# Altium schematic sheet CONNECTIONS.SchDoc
size A4; PageSetup: Record=PageOptions|CenterHorizontal=True|CenterVertical=True|PrintScale=0.70|XCorrection=1.00|YCorrection=1.00|PrintKind=0|BorderSize=5000000|LeftOffset=5|BottomOffset=0|Orientation=1|PaperLength=1000|PaperWidth=1000|Scale=100|PaperSource=7|PrintQuality=-4|MediaType=1|DitherType=10|PaperKind=A4|PrintScaleMode=1
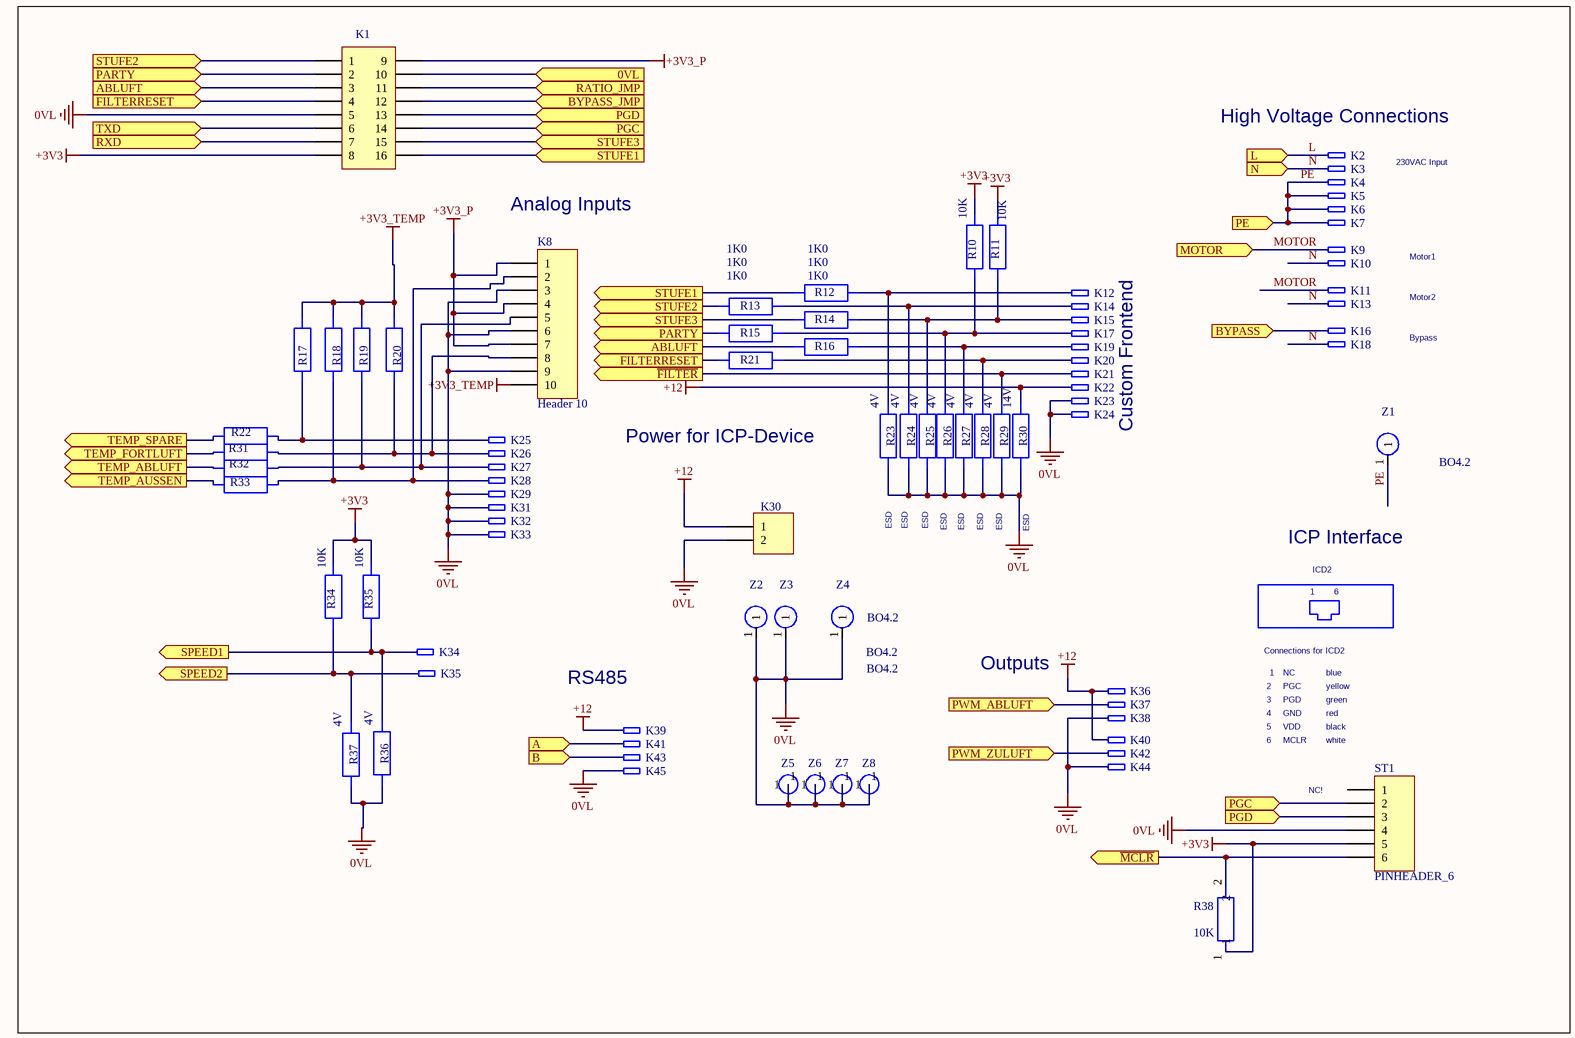
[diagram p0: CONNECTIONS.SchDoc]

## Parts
K1  PINHEADER_SMD_2MM_16POL_1  [PINHEADER_SMD_2MM_16POL]  (value not drawn)
K2  WAGO-236  [KL02X196Y0A0]  (value not drawn)
K3  WAGO-236  [KL02X196Y0A0]  (value not drawn)
K4  WAGO-236  [KL02X196Y0A0]  (value not drawn)
K5  WAGO-236  [KL02X196Y0A0]  (value not drawn)
K6  WAGO-236  [KL02X196Y0A0]  (value not drawn)
K7  WAGO-236  [KL02X196Y0A0]  (value not drawn)
K8  Header 10  [HDR1X10]
K9  WAGO-236  [KL02X196Y0A0]  (value not drawn)
K10  WAGO-236  [KL02X196Y0A0]  (value not drawn)
K11  WAGO-236  [KL02X196Y0A0]  (value not drawn)
K12  WAGO-236  [KL02X196Y0A0]  (value not drawn)
K13  WAGO-236  [KL02X196Y0A0]  (value not drawn)
K14  WAGO-236  [KL02X196Y0A0]  (value not drawn)
K15  WAGO-236  [KL02X196Y0A0]  (value not drawn)
K16  WAGO-236  [KL02X196Y0A0]  (value not drawn)
K17  WAGO-236  [KL02X196Y0A0]  (value not drawn)
K18  WAGO-236  [KL02X196Y0A0]  (value not drawn)
K19  WAGO-236  [KL02X196Y0A0]  (value not drawn)
K20  WAGO-236  [KL02X196Y0A0]  (value not drawn)
K21  WAGO-236  [KL02X196Y0A0]  (value not drawn)
K22  WAGO-236  [KL02X196Y0A0]  (value not drawn)
K23  WAGO-236  [KL02X196Y0A0]  (value not drawn)
K24  WAGO-236  [KL02X196Y0A0]  (value not drawn)
K25  WAGO-233  [KL02X0Y197A0]  (value not drawn)
K26  WAGO-233  [KL02X0Y197A0]  (value not drawn)
K27  WAGO-233  [KL02X0Y197A0]  (value not drawn)
K28  WAGO-233  [KL02X0Y197A0]  (value not drawn)
K29  WAGO-233  [KL02X0Y197A0]  (value not drawn)
K30  WUERTH_61900211121  (value not drawn)
K31  WAGO-233  [KL02X0Y197A0]  (value not drawn)
K32  WAGO-233  [KL02X0Y197A0]  (value not drawn)
K33  WAGO-233  [KL02X0Y197A0]  (value not drawn)
K34  WAGO-233  [KL02X0Y197A0]  (value not drawn)
K35  WAGO-233  [KL02X0Y197A0]  (value not drawn)
K36  WAGO-233  [KL02X0Y197A0]  (value not drawn)
K37  WAGO-233  [KL02X0Y197A0]  (value not drawn)
K38  WAGO-233  [KL02X0Y197A0]  (value not drawn)
K39  WAGO-233  [KL02X0Y197A0]  (value not drawn)
K40  WAGO-233  [KL02X0Y197A0]  (value not drawn)
K41  WAGO-233  [KL02X0Y197A0]  (value not drawn)
K42  WAGO-233  [KL02X0Y197A0]  (value not drawn)
K43  WAGO-233  [KL02X0Y197A0]  (value not drawn)
K44  WAGO-233  [KL02X0Y197A0]  (value not drawn)
K45  WAGO-233  [KL02X0Y197A0]  (value not drawn)
R10  value 10K  (hidden comment: R12/10K)
R11  value 10K  (hidden comment: R12/10K)
R12  value 1K0  (hidden comment: R12/1K0)
R13  value 1K0  (hidden comment: R12/1K0)
R14  value 1K0  (hidden comment: R12/1K0)
R15  value 1K0  (hidden comment: R12/1K0)
R16  value 1K0  (hidden comment: R12/1K0)
R17  R12/2K0  (value not drawn)
R18  R12/2K0  (value not drawn)
R19  R12/2K0  (value not drawn)
R20  R12/2K0  (value not drawn)
R21  value 1K0  (hidden comment: R12/1K0)
R22  R12/0R  (value not drawn)
R23  value 4V  (hidden comment: R12/VARISTOR_4V)
R24  value 4V  (hidden comment: R12/VARISTOR_4V)
R25  value 4V  (hidden comment: R12/VARISTOR_4V)
R26  value 4V  (hidden comment: R12/VARISTOR_4V)
R27  value 4V  (hidden comment: R12/VARISTOR_4V)
R28  value 4V  (hidden comment: R12/VARISTOR_4V)
R29  value 4V  (hidden comment: R12/VARISTOR_4V)
R30  value 14V  (hidden comment: R12/VARISTOR_14V)
R31  R12/0R  (value not drawn)
R32  R12/0R  (value not drawn)
R33  R12/0R  (value not drawn)
R34  value 10K  (hidden comment: R12/10K)
R35  value 10K  (hidden comment: R12/10K)
R36  value 4V  (hidden comment: R12/VARISTOR_4V)
R37  value 4V  (hidden comment: R12/VARISTOR_4V)
R38  value 10K  (hidden comment: R12/10K)
ST1  PINHEADER_6  [ST06S500E0A40]
Z1  BO4.2
Z2  BO4.2
Z3  BO4.2
Z4  BO4.2
Z5  BO2MM7  (value not drawn)
Z6  BO2MM7  (value not drawn)
Z7  BO2MM7  (value not drawn)
Z8  BO2MM7  (value not drawn)

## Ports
0VL, A, ABLUFT, B, BYPASS, BYPASS_JMP, FILTERRESET, L, MOTOR, N, PARTY, PE, PGC, PGD, PWM_ABLUFT, PWM_ZULUFT, RATIO_JMP, RXD, SPEED1, SPEED2, STUFE1, STUFE2, STUFE3, TEMP_ABLUFT, TEMP_AUSSEN, TEMP_FORTLUFT, TEMP_SPARE, TXD, ~{FILTER}, ~{MCLR}

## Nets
0VL: K1.5 K8.3 K8.6 K8.9 K23.1 K24.1 K29.1 K30.2 K31.1 K32.1 K33.1 K38.1 K44.1 K45.1 R23.1 R24.1 R25.1 R26.1 R27.1 R28.1 R29.1 R30.1 R36.1 R37.1 ST1.4 Z2.1 Z3.1 Z4.1 Z5.1 Z6.1 Z7.1 Z8.1
+3V3: K1.8 R10.2 R11.2 R34.2 R35.2 R38.1 ST1.5
+3V3_P: K1.9 K8.1 K8.4 K8.7
+3V3_TEMP: K8.10 R17.2 R18.2 R19.2 R20.2
+12: K22.1 K30.1 K36.1 K39.1 K40.1 R30.2
0VL: K1.10 ; port 0VL  [a separate net that carries the same name]
~{FILTER}: K21.1 R29.2 ; port ~{FILTER}
~{MCLR}: R38.2 ST1.6 ; port ~{MCLR}
A: K41.1 ; port A
ABLUFT: K1.3 R16.2 ; port ABLUFT
B: K43.1 ; port B
BYPASS: K16.1 ; port BYPASS
BYPASS_JMP: K1.12 ; port BYPASS_JMP
FILTERRESET: K1.4 R21.2 ; port FILTERRESET
L: K2.1 ; port L
MOTOR: K9.1 K11.1 ; port MOTOR
N: K3.1 K10.1 K13.1 K18.1 ; port N
PARTY: K1.2 R15.2 ; port PARTY
PE: K4.1 K5.1 K6.1 K7.1 Z1.1 ; port PE
PGC: K1.14 ST1.2 ; port PGC
PGD: K1.13 ST1.3 ; port PGD
PWM_ABLUFT: K37.1 ; port PWM_ABLUFT
PWM_ZULUFT: K42.1 ; port PWM_ZULUFT
RATIO_JMP: K1.11 ; port RATIO_JMP
RXD: K1.7 ; port RXD
SPEED1: K34.1 R35.1 R36.2 ; port SPEED1
SPEED2: K35.1 R34.1 R37.2 ; port SPEED2
STUFE1: K1.16 R12.2 ; port STUFE1
STUFE2: K1.1 R13.2 ; port STUFE2
STUFE3: K1.15 R14.2 ; port STUFE3
TEMP_ABLUFT: R32.1 ; port TEMP_ABLUFT
TEMP_AUSSEN: R33.1 ; port TEMP_AUSSEN
TEMP_FORTLUFT: R31.1 ; port TEMP_FORTLUFT
TEMP_SPARE: R22.1 ; port TEMP_SPARE
TXD: K1.6 ; port TXD
NetK8_2: K8.2 K28.1 R18.1 R33.2
NetK8_5: K8.5 K27.1 R19.1 R32.2
NetK8_8: K8.8 K26.1 R20.1 R31.2
NetK12_1: K12.1 R12.1 R23.2
NetK14_1: K14.1 R13.1 R24.2
NetK15_1: K15.1 R11.1 R14.1 R25.2
NetK17_1: K17.1 R10.1 R15.1 R26.2
NetK19_1: K19.1 R16.1 R27.2
NetK20_1: K20.1 R21.1 R28.2
NetK25_1: K25.1 R17.1 R22.2

Not connected (* = marked no-connect by the designer): ST1 1

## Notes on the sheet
- High Voltage Connections
- 230VAC Input
- (near K8) Analog Inputs
- Motor1
- Motor2
- Bypass
- Power for ICP-Device
- Custom Frontend
- ESD
- ICP Interface
- ICD2
- Connections for ICD2
- 1
- 6
- RS485
- Outputs
- 2
- 3
- 4
- GND
- PGD
- PGC
- NC
- red
- green
- yellow
- blue
- 5
- MCLR
- VDD
- (near ST1) NC!
- (near ST1) white
- black

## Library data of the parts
K1 = PINHEADER_SMD_2MM_16POL_1: DUAL ROW SMD PIN HEADER  RM2.0mm; PART DESCE: DUAL SMD PIN HEADER; Part Number: 621 016 245 821; VALUE: 16/16; MFG.#1: WUERTH; GR: ST; SUPP.ART.#1: 621 016 219 21; Geometry.Height: 5.7mm
K2-K7 K9-K24 = WAGO-236: CAGE CLAMP RM5 WAGO236 SERIES; Manufacturer Part Number 1: 236; MFG.#1: WAGO; GR: J2; SUPP.#1: FARNELL; Geometry.Height: 13.0mm
K8 = Header 10: Header, 10-Pin; PART DESCE: PINHEADER RM2,54; Part Number: WWS36G; SUPP.#1: SOSELECTRONIC; SUPP.ART.#1: 19012; GR: ST
K25-K29 K31-K45 = WAGO-233: CAGE CLAMP RM2.5; Manufacturer Part Number 1: 233; MFG.#1: WAGO; GR: J2; SUPP.#1: FARNELL; SUPP.ART.#1: 804769; Geometry.Height: 18.8mm
K30 = WUERTH_61900211121: PART DESCE: 2 POLE MALE LOCKING HEADER; MFG.#1: WUERTH; GR: J2; Geometry.Height: 11.5mm
R10 R11 R34 R35 R38 = R12/10K: PART DESCE: MINI-MELF 1% 1/4W; Geometry.Height: 3.20040mm; MFG.#1: BEYSCHLAG; GR: R; SUPP.#1: BUERKLIN; SUPP.ART.#1: 06 E 760; PCB DECAL: R02X125Y0A0
R12-R16 R21 = R12/1K0: PART DESCE: MINI-MELF 1% 1/4W or 1206; Geometry.Height: 3.20040mm; MFG.#1: BEYSCHLAG; GR: R4; SUPP.#1: BUERKLIN; SUPP.ART.#1: 06 E 664; PCB DECAL: R02X125Y0A0
R17-R20 = R12/2K0: PART DESCE: MINI-MELF 1% 1/4W; Geometry.Height: 3.20040mm; VALUE: 2K0; MFG.#1: BEYSCHLAG; GR: R; SUPP.#1: BUERKLIN; SUPP.ART.#1: 06 E 692; PCB DECAL: R02X125Y0A0
R22 R31-R33 = R12/0R: PART DESCE: MINI-MELF 1% 1/4W; Geometry.Height: 3.20040mm; VALUE: 0R; MFG.#1: BEYSCHLAG; GR: R; SUPP.#1: BUERKLIN; SUPP.ART.#1: 06 E 500; PCB DECAL: R02X125Y0A0
R23-R29 R36 R37 = R12/VARISTOR_4V: PART DESCE: VARISTOR SMD 1206 4V; MFG.#1: WUERTH; GR: R4; SUPP.ART.#1: 825 31 040; PCB DECAL: R02X125Y0A0
R30 = R12/VARISTOR_14V: PART DESCE: VARISTOR SMD 1206 14V; MFG.#1: WUERTH; GR: R4; SUPP.ART.#1: 825 31 140; PCB DECAL: R02X125Y0A0
ST1 = PINHEADER_6: PIN HEADER 6 POL RM2,54; Manufacturer Part Number 1: WWSG36; PART DESCE: PINHEADER RM2,54; VALUE: 6/0; GR: J6; Geometry.Height: 20.0mm; SUPP.#1: SOSELECTRONIC; SUPP.ART.#1: 19012
Z1-Z4 = BO4.2: PART DESCE: Drill; VALUE: 4,2mm; PCB DECAL: BO01X0Y0A166
Z5-Z8 = BO2MM7: PART DESCE: Drill; VALUE: 2,7mm; MFG.#1: PCB; GR: BO; PCB DECAL: BO01X0Y0A107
